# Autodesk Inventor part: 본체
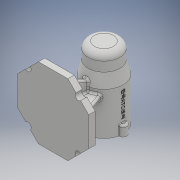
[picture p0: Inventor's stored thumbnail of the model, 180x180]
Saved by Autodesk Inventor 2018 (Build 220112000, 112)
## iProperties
Created: 2019-12
Part Number: 본체
Material: Generic
Document SubType Name: Modeling
Designer: Administrator
Density: 1 g/cm^3
Appearance: Default
Author: Administrator
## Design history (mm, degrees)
sketch "스케치1"
  geometry: L1 (23.196, -56)-(-23.196, -56); L2 (-56, -23.196)-(-56, 23.196); L3 (-23.196, 56)-(23.196, 56); L4 (56, 23.196)-(56, -23.196); L5 (23.196, 56)-(36.062, 43.134); L6 (43.134, 36.062)-(56, 23.196); L7 (56, -23.196)-(43.134, -36.062); L8 (36.062, -43.134)-(23.196, -56); L9 (-56, 23.196)-(-43.134, 36.062); L10 (-36.062, 43.134)-(-23.196, 56); L11 (-23.196, -56)-(-36.062, -43.134); L12 (-43.134, -36.062)-(-56, -23.196); A1 r 5 centre (39.598, 39.598) between (36.062, 43.134) and (43.134, 36.062); A2 r 5 centre (39.598, -39.598) between (43.134, -36.062) and (36.062, -43.134); A3 r 5 centre (-39.598, 39.598) between (-43.134, 36.062) and (-36.062, 43.134); A4 r 5 centre (-39.598, -39.598) between (-36.062, -43.134) and (-43.134, -36.062); 1 further point
  constraints: 24 end point, 8 point on circle, 4 centre point, 1 midpoint
  dimensions: "d1" = 10 diameter of A1; "d2" = 10 diameter of A2; "d3" = 10 diameter of A3; "d4" = 10 diameter of A4
extrude "돌출1" new body sketch "스케치1" distance "d5" = 10; taper "d6" = 0 deg
sketch "스케치2"
  geometry: L1 (-56, 23.196)-(-56, -23.196) reference; L2 (56, -23.196)-(56, 23.196) reference; L3 (23.196, -56)-(-23.196, -56); L4 (4, 31)-(-4, 31); L5 (-23.196, 56)-(23.196, 56); L6 (4, -38)-(-4, -38); L7 (-36, 4)-(-36, -4); L8 (36, -4)-(36, 4); L9 (-4, -38)-(-4, -4); L10 (-4, 4)-(-4, 31); L11 (4, -38)-(4, -4); L12 (4, 4)-(4, 31); L13 (-36, -4)-(-4, -4); L14 (4, -4)-(36, -4); L15 (-36, 4)-(-4, 4); L16 (4, 4)-(36, 4); 1 other entity
  constraints: 28 end point, 4 parallel, 2 horizontal, 1 other
  dimensions: "d12" = 25 dimension on L4; "d13" = 18 distance between parallel lines of L3 L6; "d14" = 20 distance between parallel lines of L1 L7; "d15" = 20 distance between parallel lines of L2 L8
extrude "돌출2" join sketch "스케치2" distance "d16" = 70; taper "d17" = 0 deg
sketch "스케치3"
  geometry: L1 (-18, 0)-(-5.134, 0) reference; L2 (0, 0)-(32.642, 70); L3 (0, 0)-(0, 70); L4 (34, 70)-(0, 70) reference; L5 (0, 70)-(32.642, 70); 1 further point
  constraints: 6 end point, 2 point on line, 1 vertical
  dimensions: "d19" = 115 deg angle of L1 L2
extrude "돌출3" cut sketch "스케치3" extent not by distance; stored distance "d20" = 70; taper "d21" = 0 deg
sketch "스케치4"
  geometry: L1 (0, 0)-(32, 0) reference; L2 (0, 0)-(25.478, 70); L3 (72, 0)-(40, 0) reference; L4 (72, 0)-(46.522, 70); L5 (79.134, 0)-(92, 0) reference; L6 (-20, 0)-(-7.134, 0) reference; L7 (0, 70)-(32, 70) reference; L8 (0, 0)-(0, 70); L9 (0, 70)-(25.478, 70); L10 (72, 70)-(40, 70) reference; L11 (72, 0)-(72, 70); L12 (72, 70)-(46.522, 70); 1 further point
  constraints: 12 end point, 2 point on line, 2 vertical
  dimensions: "d22" = 110 deg angle of L5 L4; "d23" = 110 deg angle of L6 L2
extrude "돌출4" cut sketch "스케치4" extent not by distance; stored distance "d24" = 70; taper "d25" = 0 deg
node "작업 평면1"
sketch "스케치5"
  geometry: L1 (60, 0)-(47.134, 0) reference; L2 (60, 70)-(60, 100); L3 (-52, -10)-(-52, 0) reference; L4 (60, 70)-(-52, 70); L5 (-52, 70)-(-52, 95); L6 (-52, 95)-(-27, 95); L7 (-27, 95)-(-7, 100); L8 (-7, 100)-(60, 100); 1 further point
  constraints: 12 end point, 3 perpendicular, 1 horizontal
  dimensions: "d26" = 70 distance of L1.start L2.start; "d27" = 30 distance of L2.start L2.end; "d29" = 25 distance of L4.end L5.end; "d30" = 25 distance of L5.end L6.end
revolve "회전1" sketch "스케치5" stored, may be unused: angle "d32" = 90 deg
sketch "스케치6"
  geometry: C1 r 21 at (0, 0); 1 further point
  constraints: 1 centre point
  dimensions: "d33" = 42 diameter of C1
extrude "돌출5" cut sketch "스케치6" distance "d34" = 15; taper "d35" = 0 deg
sketch "스케치7"
  geometry: C1 r 24 at (0, 0); 1 further point
  constraints: 1 centre point
  dimensions: "d36" = 48 diameter of C1
extrude "돌출6" cut sketch "스케치7" distance "d37" = 54; taper "d38" = 0 deg
sketch "스케치8"
  geometry: C1 r 21 at (0, 0); 1 further point
  constraints: 1 centre point
  dimensions: "d39" = 42 diameter of C1
extrude "돌출7" cut sketch "스케치8" distance "d40" = 12; taper "d41" = 0 deg
sketch "스케치9"
  geometry: C1 r 17.5 at (0, 0); 1 further point
  constraints: 1 centre point
  dimensions: "d42" = 35 diameter of C1
extrude "돌출8" cut sketch "스케치9" distance "d43" = 18; taper "d44" = 0 deg
sketch "스케치10"
  geometry: C1 r 16 at (0, 0); 1 further point
  constraints: 1 centre point
  dimensions: "d45" = 32 diameter of C1
extrude "돌출9" cut sketch "스케치10" distance "d46" = 4; taper "d47" = 0 deg
sketch "스케치11"
  geometry: C1 r 10.5 at (0, 0); 1 further point
  constraints: 1 centre point
  dimensions: "d48" = 21 diameter of C1
extrude "돌출10" cut sketch "스케치11" distance "d49" = 3; taper "d50" = 0 deg
fillet "모깎기1" dims "d51" = 10
fillet "모깎기2" dims "d52" = 3
fillet "모깎기3" dims "d53" = 0.3
fillet "모깎기4" dims "d54" = 3
sketch "스케치12"
  geometry: C1 r 6 at (0, 30); C2 r 6 at (30, 0); C3 r 6 at (-30, 0); C4 r 6 at (0, -30); A1 r 30 centre (0, 0) between (4, -29.732) and (-4, -29.732) reference; A2 r 30 centre (0, 0) between (4, -29.732) and (-4, -29.732) reference; 1 further point
  constraints: 4 centre point, 4 point on circle
  dimensions: "d55" = 12 diameter of C1; "d56" = 12 diameter of C2; "d57" = 12 diameter of C3; "d58" = 12 diameter of C4
extrude "돌출11" join sketch "스케치12" distance "d59" = 16; taper "d60" = 0 deg
fillet "모깎기5" dims "d61" = 3, "d62" = 1
sketch "스케치13"
  geometry: C1 r 7.5 at (0, -30) reference; A1 r 30 centre (0, -30) between (4, -59.732) and (-4, -59.732); A2 r 30 centre (0, -30) between (4, -59.732) and (-4, -59.732) reference; 5 further points
  constraints: 4 point on circle, 1 centre point, 1 coincident
  dimensions: "d63" = 60 diameter of A1
hole "구멍1" sketch "스케치13" at (0, 0), (30, -30), (0, -60), (-30, -30) diameter "d64" = 3.242; stored, may be unused: countersink angle "d68" = 90 deg, drill point angle "d70" = 118 deg; dims "d65" = 8, "d66" = 4, "d67" = 2, "d69" = 11
fillet "모깎기6" dims "d71" = 3
node "작업 평면2"
sketch "스케치14"
  geometry: L1 (21, -33.5)-(-21, -33.5) reference; L2 (0, -33.5)-(0, 92.162); L3 (21, 7.5)-(-21, 7.5); 3 further points
  constraints: 4 end point, 2 midpoint, 1 parallel, 1 vertical, 1 other
  dimensions: "d72" = 41 distance between parallel lines of L1 L3
feature "엠보싱1" sketch "스케치14" dims "d1" = 10, "d2" = 10, "d3" = 10, "d4" = 10, "d12" = 25, "d13" = 18, "d14" = 20, "d15" = 20, "d73" = 0.5, "d74" = 0
node "솔리드1"
